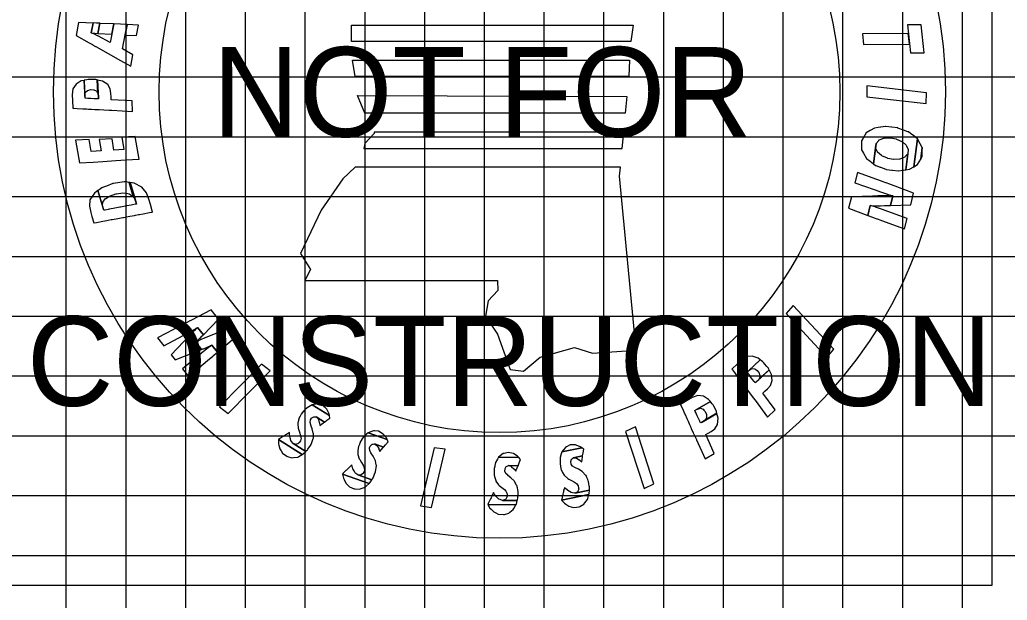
# Model space of a CAD drawing. Extents: x -10 to 342, y -5 to 215.
# Drawn here: x 313.22 to 329.75, y 185.25 to 194.96 of the extents above; entities that cross this region are included whole.
import ezdxf

# ---------------------------------------------------------------- set-up
doc = ezdxf.new("R2010")
doc.units = 0
for name, color, linetype in [('SHEET_CONSULTANT_STAMP', 7, 'Continuous'), ('SHEET_LOGO', 7, 'Continuous'), ('SHEET_LOGO_BG', 7, 'Continuous'), ('SHEET_PRELIM', 7, 'Continuous'), ('XS_SHEET_MAJOR_GRIDS', 7, 'Continuous'), ('XS_SHEET_MEDIUM_GRIDS', 7, 'Continuous'), ('XS_SHEET_MINOR_GRIDS', 7, 'Continuous')]:
    doc.layers.add(name, color=color, linetype=linetype)

msp = doc.modelspace()

# ---------------------------------------------------------------- linework, layer by layer
at = {"layer": 'SHEET_CONSULTANT_STAMP'}
msp.add_lwpolyline([(313, 185.5), (329.5, 185.5), (329.5, 202), (313, 202)], close=True, dxfattribs=at)
at = {"layer": 'SHEET_LOGO'}
for points in [[(314.906, 194.278), (315.079, 194.181), (315.115, 194.372), (314.942, 194.47), (315.019, 194.878), (314.795, 194.887), (314.737, 194.577), (314.526, 194.689), (314.522, 194.69), (314.472, 194.715), (314.47, 194.715), (314.417, 194.739), (314.448, 194.902), (314.204, 194.913), (314.163, 194.694), (314.385, 194.57), (314.438, 194.541), (314.439, 194.54), (314.489, 194.512), (314.492, 194.51), (314.702, 194.392)], [(314.475, 194.732), (314.529, 194.728), (314.561, 194.898), (314.507, 194.9), (314.505, 194.9), (314.448, 194.903), (314.417, 194.739), (314.474, 194.732)], [(314.533, 194.727), (314.763, 194.715), (314.795, 194.887), (314.565, 194.897), (314.561, 194.898), (314.529, 194.727)], [(314.985, 194.699), (315.175, 194.691), (315.208, 194.869), (315.019, 194.878)], [(318.773, 194.868), (323.486, 194.868), (323.451, 194.593), (318.773, 194.593)], [(328.094, 194.726), (327.327, 194.723), (327.346, 194.545), (328.114, 194.547)], [(328.311, 194.874), (328.078, 194.874), (328.129, 194.405), (328.362, 194.405)], [(318.79, 194.283), (323.426, 194.283), (323.417, 194.008), (318.833, 194.008)], [(314.762, 193.443), (315.11, 193.424), (315.101, 193.601), (314.753, 193.62), (314.75, 193.668), (314.747, 193.724), (314.737, 193.8), (314.694, 193.875), (314.605, 193.929), (314.524, 193.949), (314.541, 193.632), (314.54, 193.632), (314.535, 193.632), (314.512, 193.633), (314.508, 193.633), (314.468, 193.636), (314.411, 193.639), (314.382, 193.64), (314.362, 193.641), (314.328, 193.643), (314.316, 193.644), (314.314, 193.644), (314.298, 193.943), (314.251, 193.933), (314.163, 193.88), (314.111, 193.803), (314.1, 193.704), (314.104, 193.606), (314.111, 193.478), (314.111, 193.478), (314.128, 193.477), (314.184, 193.474), (314.275, 193.469), (314.323, 193.467), (314.325, 193.467), (314.337, 193.466), (314.371, 193.464), (314.391, 193.463), (314.421, 193.461), (314.477, 193.458), (314.518, 193.456), (314.521, 193.456), (314.544, 193.455), (314.55, 193.454), (314.55, 193.454), (314.629, 193.45), (314.716, 193.445), (314.756, 193.443), (314.761, 193.443)], [(314.505, 193.764), (314.53, 193.73), (314.519, 193.95), (314.495, 193.956), (314.492, 193.957), (314.451, 193.957), (314.395, 193.957), (314.366, 193.958), (314.346, 193.953), (314.312, 193.946), (314.301, 193.944), (314.298, 193.943), (314.312, 193.676), (314.313, 193.71), (314.323, 193.744), (314.355, 193.775), (314.375, 193.781), (314.404, 193.789), (314.46, 193.785), (314.502, 193.766)], [(314.537, 193.69), (314.54, 193.649), (314.524, 193.949), (314.524, 193.949), (314.519, 193.95), (314.53, 193.73)], [(328.396, 193.737), (327.402, 193.853), (327.4, 193.67), (328.394, 193.555)], [(323.383, 193.673), (323.357, 193.397), (318.997, 193.397), (318.876, 193.69)], [(319.151, 193.079), (319.151, 193.053), (318.997, 192.89), (318.979, 192.804), (323.305, 192.804), (323.331, 193.079)], [(327.338, 192.975), (327.313, 192.932), (327.313, 192.781), (327.344, 192.725), (327.394, 192.636), (327.455, 192.59), (327.511, 192.547), (327.555, 192.887), (327.556, 192.888), (327.598, 192.939), (327.603, 192.945), (327.605, 192.947), (327.685, 192.978), (327.687, 192.978), (327.691, 192.978), (327.788, 192.983), (327.791, 192.983), (327.796, 192.982), (327.888, 192.965), (327.893, 192.964), (327.897, 192.962), (327.987, 192.923), (327.99, 192.92), (327.992, 192.919), (328.06, 192.862), (328.06, 192.862), (328.066, 192.85), (328.093, 192.788), (328.085, 192.716), (328.05, 192.447), (328.113, 192.457), (328.186, 192.5), (328.246, 192.967), (328.185, 193.013), (328.128, 193.056), (328.128, 193.056), (328.096, 193.081), (328.089, 193.083), (328.088, 193.083), (328.016, 193.11), (328.015, 193.111), (328.011, 193.112), (327.921, 193.146), (327.917, 193.147), (327.912, 193.149), (327.82, 193.16), (327.814, 193.161), (327.811, 193.161), (327.716, 193.173), (327.713, 193.173), (327.71, 193.173), (327.633, 193.161), (327.631, 193.161), (327.626, 193.16), (327.59, 193.155), (327.59, 193.155), (327.526, 193.145), (327.454, 193.103), (327.388, 193.064)], [(314.995, 192.613), (315.217, 192.627), (315.152, 193.007), (314.93, 192.992), (314.965, 192.789), (314.798, 192.778), (314.766, 192.968), (314.549, 192.954), (314.582, 192.764), (314.418, 192.754), (314.384, 192.957), (314.153, 192.942), (314.219, 192.563), (314.449, 192.578), (314.612, 192.588), (314.828, 192.602)], [(328.294, 192.88), (328.246, 192.967), (328.186, 192.5), (328.25, 192.539), (328.302, 192.627), (328.327, 192.821)], [(327.546, 192.816), (327.555, 192.887), (327.511, 192.547), (327.512, 192.547)], [(327.574, 192.755), (327.546, 192.816), (327.512, 192.547), (327.544, 192.522), (327.548, 192.521), (327.55, 192.52), (327.622, 192.493), (327.624, 192.492), (327.624, 192.492), (327.628, 192.49), (327.719, 192.456), (327.723, 192.455), (327.728, 192.453), (327.82, 192.442), (327.826, 192.441), (327.83, 192.441), (327.923, 192.429), (327.927, 192.429), (327.928, 192.429), (328.005, 192.441), (328.006, 192.441), (328.013, 192.442), (328.049, 192.447), (328.05, 192.447), (328.085, 192.716), (328.084, 192.716), (328.042, 192.668), (328.034, 192.659), (328.033, 192.658), (327.954, 192.625), (327.952, 192.625), (327.948, 192.625), (327.853, 192.619), (327.849, 192.62), (327.844, 192.621), (327.752, 192.639), (327.747, 192.64), (327.743, 192.642), (327.653, 192.682), (327.649, 192.685), (327.647, 192.687), (327.579, 192.744), (327.577, 192.748)], [(328.327, 192.67), (328.327, 192.821), (328.302, 192.627), (328.327, 192.67)], [(318.833, 192.494), (318.627, 192.297), (318.266, 191.772), (317.922, 191.05), (318.085, 190.783), (317.99, 190.594), (321.215, 190.594), (321.224, 190.43), (321.061, 190.258), (321.018, 190), (321.215, 189.699), (321.43, 189.106), (321.654, 189.08), (321.929, 189.312), (322.505, 189.476), (322.806, 189.381), (323.537, 189.433), (323.262, 192.34), (323.279, 192.494)], [(327.567, 192.287), (327.245, 192.405), (327.201, 192.232), (327.524, 192.116), (327.524, 192.116), (327.603, 192.088), (327.613, 192.084), (327.677, 192.061), (327.68, 192.06), (327.744, 192.038), (327.754, 192.034), (327.835, 192.012), (327.794, 191.852), (328.134, 191.862), (328.183, 192.059), (327.875, 192.173), (327.797, 192.202), (327.786, 192.206), (327.723, 192.229), (327.72, 192.23), (327.656, 192.254), (327.646, 192.258)], [(315.443, 191.742), (315.444, 191.742), (315.407, 191.866), (315.38, 191.956), (315.341, 192.06), (315.266, 192.16), (315.135, 192.227), (315.067, 192.235), (315.175, 191.874), (315.175, 191.874), (315.16, 191.871), (315.108, 191.861), (315.088, 191.857), (315.012, 191.843), (314.908, 191.823), (314.897, 191.821), (314.783, 191.8), (314.716, 191.787), (314.702, 191.785), (314.651, 191.775), (314.63, 191.771), (314.628, 191.771), (314.53, 192.099), (314.471, 192.058), (314.395, 191.944), (314.386, 191.837), (314.409, 191.735), (314.428, 191.669), (314.46, 191.56), (314.461, 191.56), (314.468, 191.561), (314.507, 191.568), (314.611, 191.588), (314.679, 191.6), (314.681, 191.601), (314.702, 191.604), (314.753, 191.614), (314.767, 191.617), (314.834, 191.629), (314.947, 191.65), (314.959, 191.652), (315.063, 191.672), (315.139, 191.686), (315.159, 191.689), (315.211, 191.699), (315.226, 191.702), (315.226, 191.702), (315.288, 191.713), (315.393, 191.733), (315.436, 191.741)], [(315.053, 192.046), (315.121, 192.002), (315.051, 192.238), (314.994, 192.245), (314.972, 192.248), (314.895, 192.236), (314.79, 192.22), (314.779, 192.216), (314.671, 192.176), (314.607, 192.153), (314.595, 192.144), (314.55, 192.113), (314.55, 192.113), (314.532, 192.101), (314.53, 192.099), (314.618, 191.803), (314.606, 191.851), (314.612, 191.906), (314.65, 191.96), (314.663, 191.968), (314.722, 192.007), (314.83, 192.045), (314.841, 192.046), (314.947, 192.061), (315.031, 192.049)], [(315.121, 192.001), (315.156, 191.938), (315.067, 192.236), (315.051, 192.238)], [(315.156, 191.938), (315.175, 191.874), (315.067, 192.235), (315.067, 192.236)], [(327.496, 192.008), (327.141, 191.994), (327.093, 191.804), (327.415, 191.685), (327.456, 191.848), (327.542, 191.844), (327.553, 191.844), (327.623, 191.846), (327.626, 191.846), (327.696, 191.848), (327.707, 191.849), (327.794, 191.852), (327.835, 192.012), (327.75, 192.016), (327.739, 192.017), (327.669, 192.015), (327.665, 192.015), (327.595, 192.012), (327.584, 192.011)], [(327.537, 191.826), (327.456, 191.848), (327.415, 191.685), (327.494, 191.656), (327.504, 191.652), (327.568, 191.629), (327.571, 191.628), (327.634, 191.604), (327.645, 191.601), (328.032, 191.458), (328.075, 191.631), (327.688, 191.773), (327.678, 191.777), (327.614, 191.8), (327.611, 191.801), (327.547, 191.823)], [(315.935, 189.85), (315.524, 189.636), (315.633, 189.502), (316.041, 189.72), (316.06, 189.73), (316.066, 189.733), (316.066, 189.734), (316.068, 189.735), (316.068, 189.735), (316.106, 189.757), (316.113, 189.76), (316.125, 189.767), (316.128, 189.769), (316.129, 189.769), (316.13, 189.77), (316.172, 189.796), (316.176, 189.799), (316.196, 189.811), (316.294, 189.69), (316.549, 189.952), (316.424, 190.105), (316.095, 189.934), (316.075, 189.924), (316.07, 189.921), (316.026, 189.898), (316.025, 189.897), (316.024, 189.897), (316.021, 189.895), (316.009, 189.889), (316.002, 189.885), (315.962, 189.865), (315.96, 189.864), (315.954, 189.86)], [(326.048, 190.042), (326.729, 189.31), (326.849, 189.447), (326.168, 190.18)], [(316.07, 189.684), (315.755, 189.352), (315.823, 189.268), (316.265, 189.443), (316.167, 189.565), (316.182, 189.579), (316.187, 189.584), (316.189, 189.586), (316.22, 189.616), (316.226, 189.622), (316.236, 189.631), (316.238, 189.634), (316.239, 189.635), (316.24, 189.635), (316.274, 189.67), (316.278, 189.674), (316.294, 189.69), (316.196, 189.811), (316.179, 189.795), (316.176, 189.792), (316.141, 189.757), (316.14, 189.756), (316.139, 189.755), (316.136, 189.753), (316.127, 189.743), (316.122, 189.738), (316.091, 189.706), (316.089, 189.705), (316.084, 189.699)], [(316.186, 189.575), (316.167, 189.565), (316.265, 189.443), (316.286, 189.452), (316.286, 189.452), (316.293, 189.454), (316.295, 189.455), (316.337, 189.472), (316.345, 189.475), (316.345, 189.475), (316.358, 189.48), (316.358, 189.481), (316.361, 189.482), (316.363, 189.482), (316.364, 189.483), (316.364, 189.483), (316.409, 189.504), (316.414, 189.507), (316.435, 189.517), (316.531, 189.398), (316.809, 189.632), (316.685, 189.785), (316.333, 189.641), (316.312, 189.633), (316.307, 189.63), (316.26, 189.61), (316.259, 189.61), (316.258, 189.609), (316.254, 189.608), (316.242, 189.602), (316.234, 189.599), (316.195, 189.579), (316.192, 189.578)], [(316.295, 189.407), (315.944, 189.119), (316.047, 188.992), (316.395, 189.284), (316.411, 189.298), (316.416, 189.302), (316.418, 189.304), (316.418, 189.304), (316.452, 189.332), (316.458, 189.337), (316.468, 189.345), (316.47, 189.348), (316.471, 189.348), (316.472, 189.349), (316.51, 189.381), (316.514, 189.384), (316.531, 189.398), (316.435, 189.517), (316.417, 189.503), (316.413, 189.5), (316.374, 189.471), (316.373, 189.47), (316.372, 189.469), (316.369, 189.467), (316.359, 189.459), (316.352, 189.454), (316.318, 189.427), (316.316, 189.425), (316.311, 189.421)], [(325.528, 188.594), (325.737, 188.314), (325.867, 188.434), (325.659, 188.714), (325.694, 188.746), (325.735, 188.785), (325.787, 188.841), (325.817, 188.922), (325.802, 189.025), (325.765, 189.1), (325.532, 188.884), (325.532, 188.884), (325.529, 188.889), (325.515, 188.907), (325.513, 188.91), (325.488, 188.943), (325.455, 188.988), (325.437, 189.012), (325.425, 189.028), (325.405, 189.055), (325.398, 189.065), (325.396, 189.066), (325.616, 189.27), (325.578, 189.3), (325.481, 189.333), (325.389, 189.324), (325.306, 189.27), (325.233, 189.203), (325.139, 189.116), (325.139, 189.116), (325.149, 189.102), (325.183, 189.057), (325.237, 188.984), (325.266, 188.946), (325.267, 188.944), (325.274, 188.935), (325.295, 188.908), (325.307, 188.891), (325.324, 188.868), (325.358, 188.822), (325.382, 188.79), (325.384, 188.787), (325.398, 188.768), (325.401, 188.764), (325.402, 188.764), (325.449, 188.7), (325.501, 188.63), (325.525, 188.599), (325.528, 188.594)], [(325.611, 188.996), (325.601, 188.956), (325.763, 189.105), (325.752, 189.127), (325.751, 189.13), (325.725, 189.161), (325.689, 189.205), (325.67, 189.227), (325.654, 189.24), (325.627, 189.261), (325.618, 189.268), (325.616, 189.27), (325.42, 189.088), (325.446, 189.109), (325.479, 189.124), (325.523, 189.119), (325.54, 189.107), (325.565, 189.09), (325.598, 189.045), (325.61, 189)], [(317.268, 189.198), (316.567, 188.484), (316.71, 188.371), (317.411, 189.085)], [(325.574, 188.924), (325.545, 188.896), (325.765, 189.1), (325.765, 189.1), (325.763, 189.105), (325.601, 188.956)], [(324.549, 187.931), (324.692, 187.613), (324.845, 187.702), (324.702, 188.02), (324.744, 188.044), (324.792, 188.073), (324.855, 188.116), (324.902, 188.189), (324.909, 188.293), (324.89, 188.374), (324.616, 188.214), (324.615, 188.214), (324.613, 188.219), (324.604, 188.24), (324.602, 188.243), (324.586, 188.28), (324.562, 188.332), (324.55, 188.359), (324.542, 188.377), (324.528, 188.408), (324.523, 188.419), (324.522, 188.421), (324.781, 188.572), (324.751, 188.609), (324.663, 188.663), (324.571, 188.674), (324.478, 188.639), (324.393, 188.59), (324.282, 188.525), (324.282, 188.525), (324.289, 188.509), (324.312, 188.458), (324.35, 188.375), (324.369, 188.331), (324.37, 188.329), (324.375, 188.319), (324.389, 188.288), (324.397, 188.269), (324.409, 188.242), (324.432, 188.191), (324.449, 188.154), (324.45, 188.15), (324.46, 188.129), (324.462, 188.124), (324.462, 188.124), (324.495, 188.052), (324.531, 187.972), (324.547, 187.936), (324.549, 187.931)], [(317.847, 187.854), (317.797, 187.869), (318.007, 187.737), (318.017, 187.747), (318.023, 187.752), (318.038, 187.767), (318.045, 187.778), (318.054, 187.791), (318.074, 187.822), (318.097, 187.856), (318.1, 187.861), (318.11, 187.887), (318.122, 187.92), (318.134, 187.954), (318.135, 187.965), (318.136, 188.037), (318.134, 188.046), (318.116, 188.118), (318.092, 188.18), (318.092, 188.181), (318.081, 188.224), (318.086, 188.265), (318.088, 188.269), (318.107, 188.295), (318.107, 188.296), (318.109, 188.298), (318.112, 188.3), (318.145, 188.319), (318.16, 188.318), (318.16, 188.318), (318.184, 188.316), (318.321, 188.23), (318.362, 188.259), (318.412, 188.297), (318.404, 188.34), (318.117, 188.52), (318.086, 188.502), (318.029, 188.469), (317.995, 188.435), (317.987, 188.427), (317.982, 188.422), (317.957, 188.397), (317.955, 188.395), (317.953, 188.393), (317.936, 188.365), (317.933, 188.361), (317.914, 188.33), (317.898, 188.303), (317.898, 188.302), (317.887, 188.262), (317.873, 188.21), (317.873, 188.202), (317.879, 188.126), (317.884, 188.111), (317.901, 188.059), (317.92, 188.006), (317.928, 187.969), (317.93, 187.961), (317.921, 187.917), (317.9, 187.888), (317.89, 187.875), (317.877, 187.868), (317.855, 187.858)], [(318.15, 188.524), (318.118, 188.52), (318.404, 188.34), (318.398, 188.368), (318.367, 188.434), (318.362, 188.444), (318.296, 188.506), (318.296, 188.506), (318.232, 188.526), (318.211, 188.532)], [(324.717, 188.306), (324.698, 188.268), (324.889, 188.379), (324.883, 188.403), (324.882, 188.406), (324.864, 188.443), (324.838, 188.493), (324.825, 188.519), (324.812, 188.535), (324.79, 188.561), (324.783, 188.57), (324.781, 188.572), (324.55, 188.437), (324.58, 188.452), (324.615, 188.459), (324.658, 188.445), (324.672, 188.429), (324.692, 188.407), (324.715, 188.356), (324.717, 188.31)], [(318.236, 188.214), (318.243, 188.172), (318.271, 188.193), (318.273, 188.194), (318.277, 188.197), (318.306, 188.218), (318.312, 188.223), (318.312, 188.223), (318.321, 188.23), (318.184, 188.316), (318.216, 188.283), (318.219, 188.273), (318.235, 188.223), (318.236, 188.218)], [(324.665, 188.243), (324.63, 188.222), (324.89, 188.374), (324.89, 188.374), (324.889, 188.379), (324.698, 188.268)], [(323.362, 188.073), (323.67, 187.121), (323.837, 187.195), (323.528, 188.147)], [(317.567, 187.948), (317.553, 187.938), (317.95, 187.688), (317.966, 187.697), (318.007, 187.737), (317.797, 187.869), (317.771, 187.902), (317.758, 187.919), (317.75, 187.948), (317.746, 187.965), (317.741, 187.988), (317.738, 188.033), (317.737, 188.057), (317.718, 188.045), (317.685, 188.024), (317.669, 188.014), (317.658, 188.006), (317.639, 187.994), (317.632, 187.989), (317.619, 187.981)], [(317.619, 187.707), (317.691, 187.657), (317.704, 187.653), (317.776, 187.632), (317.804, 187.635), (317.874, 187.645), (317.892, 187.655), (317.95, 187.688), (317.553, 187.938), (317.554, 187.867), (317.56, 187.842), (317.574, 187.78), (317.595, 187.746)], [(318.931, 187.341), (318.879, 187.346), (319.112, 187.262), (319.12, 187.274), (319.124, 187.28), (319.136, 187.298), (319.14, 187.31), (319.146, 187.325), (319.159, 187.359), (319.174, 187.397), (319.176, 187.403), (319.18, 187.431), (319.185, 187.466), (319.19, 187.501), (319.187, 187.512), (319.173, 187.583), (319.169, 187.591), (319.136, 187.657), (319.1, 187.713), (319.099, 187.714), (319.079, 187.754), (319.075, 187.794), (319.077, 187.798), (319.089, 187.829), (319.089, 187.829), (319.09, 187.831), (319.093, 187.834), (319.121, 187.861), (319.136, 187.862), (319.136, 187.862), (319.16, 187.865), (319.312, 187.811), (319.345, 187.849), (319.387, 187.896), (319.369, 187.936), (319.051, 188.05), (319.024, 188.026), (318.975, 187.981), (318.949, 187.941), (318.943, 187.931), (318.94, 187.926), (318.921, 187.896), (318.919, 187.893), (318.917, 187.89), (318.907, 187.859), (318.905, 187.855), (318.893, 187.82), (318.883, 187.791), (318.883, 187.79), (318.881, 187.748), (318.878, 187.695), (318.881, 187.687), (318.903, 187.614), (318.911, 187.601), (318.939, 187.554), (318.969, 187.506), (318.985, 187.471), (318.988, 187.464), (318.99, 187.42), (318.975, 187.386), (318.968, 187.371), (318.957, 187.362), (318.938, 187.347)], [(319.082, 188.061), (319.051, 188.05), (319.369, 187.936), (319.358, 187.963), (319.312, 188.021), (319.306, 188.029), (319.228, 188.075), (319.228, 188.075), (319.161, 188.081), (319.14, 188.082)], [(319.233, 187.777), (319.248, 187.737), (319.271, 187.764), (319.273, 187.766), (319.276, 187.769), (319.3, 187.797), (319.305, 187.802), (319.305, 187.802), (319.312, 187.811), (319.16, 187.865), (319.198, 187.84), (319.203, 187.831), (319.23, 187.785), (319.232, 187.781)], [(320.16, 187.8), (319.931, 186.826), (320.112, 186.803), (320.341, 187.777)], [(322.56, 187.065), (322.513, 187.041), (322.756, 187.091), (322.757, 187.105), (322.757, 187.112), (322.758, 187.134), (322.756, 187.146), (322.753, 187.162), (322.746, 187.198), (322.739, 187.238), (322.738, 187.244), (322.727, 187.27), (322.713, 187.302), (322.699, 187.335), (322.691, 187.343), (322.643, 187.396), (322.635, 187.401), (322.572, 187.441), (322.512, 187.47), (322.511, 187.47), (322.473, 187.494), (322.449, 187.526), (322.448, 187.531), (322.443, 187.563), (322.443, 187.563), (322.443, 187.566), (322.444, 187.57), (322.454, 187.607), (322.466, 187.616), (322.465, 187.616), (322.485, 187.631), (322.643, 187.663), (322.652, 187.713), (322.663, 187.775), (322.627, 187.8), (322.295, 187.733), (322.285, 187.698), (322.266, 187.634), (322.265, 187.586), (322.265, 187.575), (322.265, 187.569), (322.264, 187.534), (322.264, 187.53), (322.264, 187.527), (322.271, 187.495), (322.272, 187.49), (322.28, 187.455), (322.286, 187.424), (322.287, 187.424), (322.307, 187.387), (322.332, 187.34), (322.338, 187.334), (322.396, 187.283), (322.409, 187.276), (322.458, 187.25), (322.508, 187.225), (322.539, 187.203), (322.546, 187.199), (322.57, 187.162), (322.575, 187.126), (322.577, 187.109), (322.572, 187.096), (322.563, 187.073)], [(322.316, 187.758), (322.296, 187.733), (322.627, 187.8), (322.603, 187.817), (322.535, 187.843), (322.525, 187.847), (322.435, 187.846), (322.435, 187.846), (322.374, 187.816), (322.355, 187.806)], [(321.35, 186.932), (321.299, 186.919), (321.547, 186.915), (321.551, 186.929), (321.553, 186.936), (321.558, 186.957), (321.558, 186.969), (321.559, 186.986), (321.561, 187.022), (321.563, 187.063), (321.563, 187.069), (321.557, 187.096), (321.551, 187.131), (321.544, 187.166), (321.538, 187.176), (321.502, 187.238), (321.496, 187.245), (321.443, 187.297), (321.391, 187.338), (321.39, 187.339), (321.358, 187.37), (321.341, 187.407), (321.341, 187.412), (321.344, 187.444), (321.343, 187.444), (321.344, 187.447), (321.346, 187.451), (321.364, 187.485), (321.377, 187.491), (321.377, 187.491), (321.399, 187.501), (321.561, 187.499), (321.58, 187.545), (321.604, 187.603), (321.574, 187.636), (321.236, 187.642), (321.218, 187.61), (321.186, 187.552), (321.175, 187.505), (321.172, 187.494), (321.171, 187.488), (321.162, 187.454), (321.162, 187.45), (321.161, 187.447), (321.161, 187.415), (321.161, 187.41), (321.161, 187.373), (321.161, 187.343), (321.161, 187.342), (321.172, 187.301), (321.187, 187.25), (321.192, 187.243), (321.237, 187.181), (321.248, 187.171), (321.29, 187.136), (321.333, 187.1), (321.359, 187.072), (321.365, 187.066), (321.381, 187.025), (321.377, 186.989), (321.376, 186.972), (321.368, 186.96), (321.355, 186.939)], [(321.262, 187.662), (321.236, 187.642), (321.574, 187.636), (321.555, 187.657), (321.493, 187.698), (321.485, 187.703), (321.396, 187.722), (321.396, 187.722), (321.331, 187.706), (321.31, 187.701)], [(322.593, 187.594), (322.627, 187.567), (322.633, 187.602), (322.633, 187.605), (322.634, 187.609), (322.64, 187.645), (322.641, 187.652), (322.641, 187.652), (322.643, 187.663), (322.485, 187.631), (322.531, 187.629), (322.539, 187.624), (322.586, 187.599), (322.59, 187.596)], [(318.637, 187.373), (318.625, 187.36), (319.067, 187.202), (319.081, 187.214), (319.112, 187.262), (318.879, 187.346), (318.847, 187.372), (318.829, 187.386), (318.816, 187.413), (318.808, 187.428), (318.798, 187.45), (318.786, 187.492), (318.779, 187.516), (318.763, 187.5), (318.735, 187.472), (318.723, 187.459), (318.713, 187.45), (318.697, 187.433), (318.691, 187.427), (318.681, 187.417)], [(321.496, 187.442), (321.524, 187.409), (321.537, 187.441), (321.538, 187.444), (321.54, 187.448), (321.554, 187.482), (321.556, 187.488), (321.556, 187.488), (321.561, 187.499), (321.399, 187.501), (321.443, 187.49), (321.451, 187.483), (321.491, 187.448), (321.494, 187.444)], [(318.74, 187.148), (318.821, 187.115), (318.835, 187.114), (318.91, 187.109), (318.936, 187.119), (319.002, 187.143), (319.017, 187.157), (319.067, 187.202), (318.625, 187.36), (318.642, 187.291), (318.653, 187.268), (318.68, 187.21), (318.708, 187.182)], [(322.293, 186.939), (322.289, 186.922), (322.749, 187.016), (322.754, 187.033), (322.756, 187.091), (322.513, 187.041), (322.472, 187.047), (322.45, 187.05), (322.425, 187.066), (322.41, 187.075), (322.391, 187.088), (322.358, 187.119), (322.34, 187.136), (322.335, 187.114), (322.325, 187.075), (322.321, 187.057), (322.318, 187.044), (322.313, 187.022), (322.311, 187.014), (322.307, 186.999)], [(321.062, 186.867), (321.054, 186.852), (321.524, 186.844), (321.533, 186.859), (321.547, 186.915), (321.299, 186.919), (321.26, 186.933), (321.239, 186.941), (321.218, 186.963), (321.206, 186.975), (321.19, 186.992), (321.164, 187.028), (321.15, 187.049), (321.14, 187.029), (321.123, 186.993), (321.115, 186.976), (321.109, 186.964), (321.099, 186.944), (321.096, 186.936), (321.089, 186.923)], [(322.497, 186.8), (322.583, 186.814), (322.595, 186.82), (322.662, 186.855), (322.68, 186.877), (322.724, 186.932), (322.73, 186.951), (322.749, 187.016), (322.289, 186.922), (322.339, 186.872), (322.36, 186.857), (322.414, 186.822), (322.452, 186.812)], [(321.231, 186.688), (321.318, 186.682), (321.332, 186.686), (321.405, 186.705), (321.426, 186.723), (321.481, 186.767), (321.491, 186.785), (321.524, 186.844), (321.055, 186.852), (321.092, 186.791), (321.11, 186.773), (321.155, 186.727), (321.19, 186.709)]]:
    msp.add_lwpolyline(points, close=True, dxfattribs=at)
for radius in [7.464, 5.697]:
    msp.add_circle((321.25, 193.75), radius, dxfattribs=at)
at = {"layer": 'SHEET_LOGO_BG'}
msp.add_lwpolyline([(313, 185.5), (329.5, 185.5), (329.5, 202), (313, 202)], close=True, dxfattribs=at)
at = {"layer": 'SHEET_PRELIM'}
msp.add_lwpolyline([(313, 185.5), (329.5, 185.5), (329.5, 202), (313, 202)], close=True, dxfattribs=at)
at = {"layer": 'XS_SHEET_MAJOR_GRIDS'}
for p, q in [((320, 0), (320, 202)), ((5, 190), (340, 190))]:
    msp.add_line(p, q, dxfattribs=at)
at = {"layer": 'XS_SHEET_MEDIUM_GRIDS'}
for p, q in [((315, 0), (315, 202)), ((325, 0), (325, 202))]:
    msp.add_line(p, q, dxfattribs=at)
at = {"layer": 'XS_SHEET_MINOR_GRIDS'}
for p, q in [((314, 0), (314, 202)), ((316, 0), (316, 202)), ((317, 0), (317, 202)), ((318, 0), (318, 202)), ((319, 0), (319, 202)), ((321, 0), (321, 202)), ((322, 0), (322, 202)), ((323, 0), (323, 202)), ((324, 0), (324, 202)), ((326, 0), (326, 202)), ((327, 0), (327, 202)), ((328, 0), (328, 202)), ((329, 0), (329, 202)), ((5, 194), (340, 194)), ((5, 193), (340, 193)), ((5, 192), (340, 192)), ((5, 191), (340, 191)), ((5, 189), (340, 189)), ((5, 188), (340, 188)), ((5, 187), (340, 187)), ((5, 186), (340, 186))]:
    msp.add_line(p, q, dxfattribs=at)

# ---------------------------------------------------------------- texts
at = {"layer": 'SHEET_PRELIM'}
for s, p in [('NOT FOR', (316.45, 193)), ('CONSTRUCTION', (313.34, 188.5))]:
    msp.add_text(s, height=1.5, dxfattribs=at).set_placement(p)

doc.saveas('drawing.dxf')
